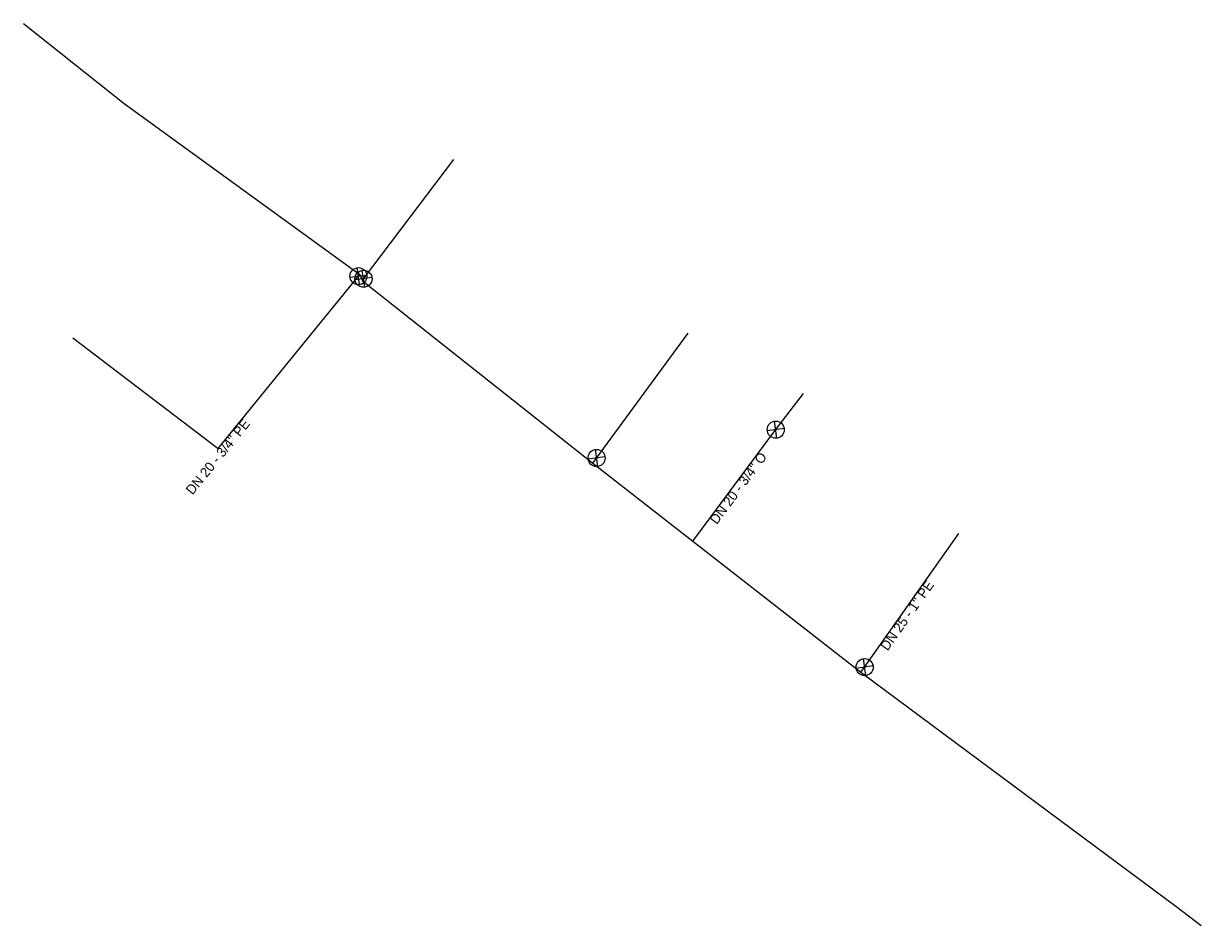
# Model space of a CAD drawing. Extents: x -492321 to -492053, y -1126159 to -1125902.
# Drawn here: x -492225.3 to -492170.4, y -1125944.6 to -1125902.3 of the extents above; entities that cross this region are included whole.
import ezdxf

# ---------------------------------------------------------------- set-up
doc = ezdxf.new("R2010")
doc.units = 0
for name, color, linetype in [('_pripojka_prevzato_z_dokumentace_', 7, 'Continuous'), ('_voda_smvak_prevzato_z_dokumentace_', 7, 'Continuous'), ('Default', 7, 'Continuous'), ('MoLevel 53', 7, 'Continuous'), ('MoLevel 55', 7, 'Continuous')]:
    doc.layers.add(name, color=color, linetype=linetype)

# ---------------------------------------------------------------- blocks, each defined once
blk = doc.blocks.new('_uzaver_pripojka_')
at = {"layer": 'Default'}
for p, q in [((-0.000035, -0.000035), (0.000035, 0.000035)), ((0.000035, -0.000035), (-0.000035, 0.000035))]:
    blk.add_line(p, q, dxfattribs=at)
for radius in [0.00005, 0.0000025]:
    blk.add_circle((0, 0), radius, dxfattribs=at)

msp = doc.modelspace()

# ---------------------------------------------------------------- linework, layer by layer
at = {"layer": '_pripojka_prevzato_z_dokumentace_'}
for p, q in [((-492190.02, -1125921.35), (-492188.72, -1125919.65)), ((-492193.91, -1125926.58), (-492190.02, -1125921.35))]:
    msp.add_line(p, q, dxfattribs=at)
for points in [[(-492209.4, -1125914.36), (-492209.35, -1125914.27), (-492205.109, -1125908.682)], [(-492212.334, -1125917.52), (-492209.59, -1125914.15), (-492209.52, -1125914.07)], [(-492198.6, -1125922.92), (-492198.42, -1125922.68), (-492194.12, -1125916.83)], [(-492222.983, -1125917.046), (-492216.171, -1125922.234), (-492212.334, -1125917.52)], [(-492186.03, -1125932.73), (-492185.85, -1125932.49), (-492181.428, -1125926.224)]]:
    msp.add_lwpolyline(points, dxfattribs=at)
at = {"layer": '_voda_smvak_prevzato_z_dokumentace_'}
msp.add_lwpolyline([(-492225.3, -1125902.29), (-492220.567, -1125906.046), (-492209.52, -1125914.07), (-492209.4, -1125914.36), (-492198.6, -1125922.92), (-492193.91, -1125926.58), (-492186.03, -1125932.73), (-492171.197, -1125943.758), (-492170.066, -1125944.617)], dxfattribs=at)

# ---------------------------------------------------------------- block references
at = {"layer": 'MoLevel 53'}
for p, xscale, yscale, rotation in [((-492209.59, -1125914.15), 7999.999999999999, 8000.000000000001, -37.444227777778), ((-492209.35, -1125914.27), 8000, 8000, 53.46343888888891), ((-492190.02, -1125921.35), 8000, 7999.999999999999, 53.4716222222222), ((-492198.42, -1125922.68), 8000, 7999.999999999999, 53.4716222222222), ((-492185.85, -1125932.49), 8000, 7999.999999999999, 53.4716222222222)]:
    msp.add_blockref('_uzaver_pripojka_', p, dxfattribs=dict(at, xscale=xscale, yscale=yscale, rotation=rotation))

# ---------------------------------------------------------------- texts
at = {"layer": 'MoLevel 55'}
for s, rotation, p in [("DN 20 - 3/4'' PE", 50.8518, (-492217.371, -1125924.438)), ("DN 20 - 3/4'' O", 53.3587, (-492192.784, -1125925.828)), ("DN 25 - 1'' PE", 54.7879, (-492184.775, -1125931.756))]:
    msp.add_text(s, height=0.455, rotation=rotation, dxfattribs=at).set_placement(p)

doc.saveas('drawing.dxf')
